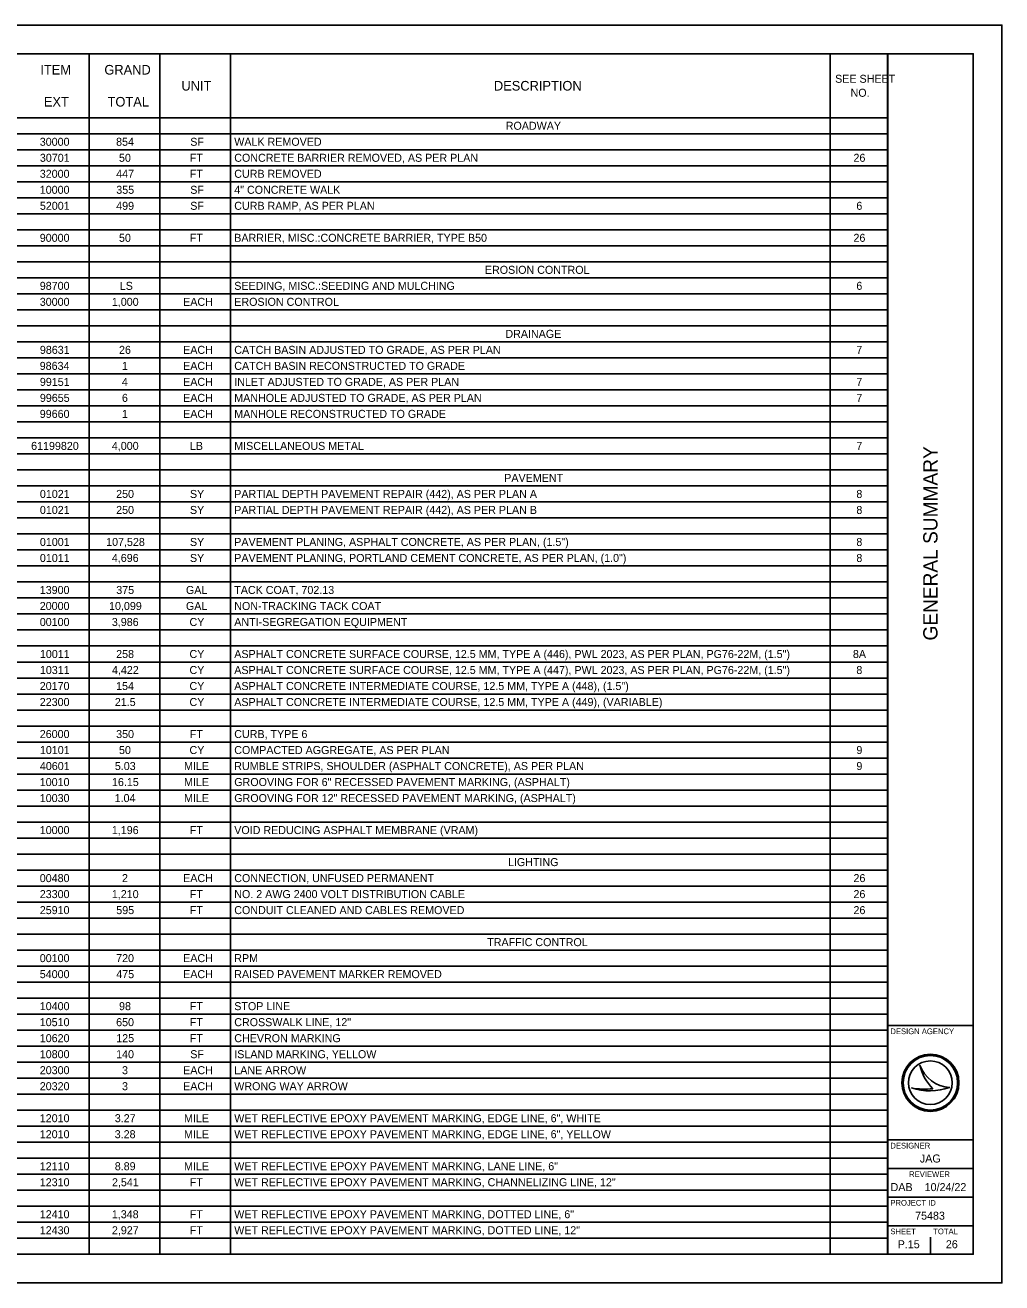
# Model space of a CAD drawing. Extents: x -32.9 to 34, y 0 to 22.
# Drawn here: x 16.92 to 34, y 0 to 22 of the extents above; entities that cross this region are included whole.
import ezdxf

# ---------------------------------------------------------------- set-up
doc = ezdxf.new("R2010")
doc.units = 0
for name, color, linetype in [('SH_Border', 7, 'Continuous'), ('SH_Cut_Line', 7, 'Continuous'), ('SH_Data', 7, 'Continuous'), ('SH_Text', 7, 'Continuous')]:
    doc.layers.add(name, color=color, linetype=linetype)

msp = doc.modelspace()

# ---------------------------------------------------------------- linework, layer by layer
at = {"layer": 'SH_Border'}
for p, q in [((32, 0.5), (32, 21.5)), ((32, 4.5), (33.5, 4.5)), ((32, 2.5), (33.5, 2.5)), ((32, 2), (33.5, 2)), ((32, 1.5), (33.5, 1.5)), ((32, 1), (33.5, 1))]:
    msp.add_line(p, q, dxfattribs=at)
msp.add_lwpolyline([(1.5, 21.5), (33.5, 21.5), (33.5, 0.5), (1.5, 0.5)], close=True, dxfattribs=at)
at = {"layer": 'SH_Cut_Line'}
msp.add_lwpolyline([(0, 0), (34, 0), (34, 22), (0, 22)], close=True, dxfattribs=at)
at = {"layer": 'SH_Data'}
for p, q in [((32.567, 3.81), (32.567, 3.81)), ((32.417, 3.41), (32.417, 3.41)), ((32.75, 3.5), (32.75, 3.5)), ((33.087, 3.419), (33.087, 3.419)), ((32.375, 0.675), (32.375, 0.675)), ((32.75, 0.5), (32.75, 0.8))]:
    msp.add_line(p, q, dxfattribs=at)
for radius in [0.5, 0.477, 0.477, 0.382]:
    msp.add_circle((32.75, 3.5), radius, dxfattribs=at)
for centre, radius, start, end in [((33.116, 3.998), 0.58, 198.9257, 198.9319), ((33.347, 3.97), 0.796, 191.6379, 191.6421), ((33.116, 3.998), 0.58, 198.9319, 267.1657), ((33.347, 3.97), 0.796, 191.6421, 226.0947), ((32.739, 4.37), 1.013, 251.4576, 290.0832), ((32.648, 4.654), 1.266, 259.4964, 259.4995), ((32.739, 4.37), 1.013, 251.4527, 251.4576), ((32.648, 4.654), 1.266, 259.4995, 276.6672)]:
    msp.add_arc(centre, radius, start, end, dxfattribs=at)
at = {"layer": 'SH_Text'}
for p, q in [((1.5, 21.5), (32.004, 21.5)), ((18.036, 21.5), (18.036, 0.5)), ((19.272, 21.5), (19.272, 0.5)), ((20.507, 21.5), (20.507, 0.5)), ((30.999, 21.5), (30.999, 0.5)), ((32.004, 21.5), (32.004, 0.5)), ((1.5, 20.38), (32.004, 20.38)), ((1.5, 20.1), (32.004, 20.1)), ((1.5, 19.82), (32.004, 19.82)), ((1.5, 19.54), (32.004, 19.54)), ((1.5, 19.26), (32.004, 19.26)), ((1.5, 18.98), (32.004, 18.98)), ((1.5, 18.7), (32.004, 18.7)), ((1.5, 18.42), (32.004, 18.42)), ((1.5, 18.14), (32.004, 18.14)), ((1.5, 17.86), (32.004, 17.86)), ((1.5, 17.58), (32.004, 17.58)), ((1.5, 17.3), (32.004, 17.3)), ((1.5, 17.02), (32.004, 17.02)), ((1.5, 16.74), (32.004, 16.74)), ((1.5, 16.46), (32.004, 16.46)), ((1.5, 16.18), (32.004, 16.18)), ((1.5, 15.9), (32.004, 15.9)), ((1.5, 15.62), (32.004, 15.62)), ((1.5, 15.34), (32.004, 15.34)), ((1.5, 15.06), (32.004, 15.06)), ((1.5, 14.78), (32.004, 14.78)), ((1.5, 14.5), (32.004, 14.5)), ((1.5, 14.22), (32.004, 14.22)), ((1.5, 13.94), (32.004, 13.94)), ((1.5, 13.66), (32.004, 13.66)), ((1.5, 13.38), (32.004, 13.38)), ((1.5, 13.1), (32.004, 13.1)), ((1.5, 12.82), (32.004, 12.82)), ((1.5, 12.54), (32.004, 12.54)), ((1.5, 12.26), (32.004, 12.26)), ((1.5, 11.98), (32.004, 11.98)), ((1.5, 11.7), (32.004, 11.7)), ((1.5, 11.42), (32.004, 11.42)), ((1.5, 11.14), (32.004, 11.14)), ((1.5, 10.86), (32.004, 10.86)), ((1.5, 10.58), (32.004, 10.58)), ((1.5, 10.3), (32.004, 10.3)), ((1.5, 10.02), (32.004, 10.02)), ((1.5, 9.74), (32.004, 9.74)), ((1.5, 9.46), (32.004, 9.46)), ((1.5, 9.18), (32.004, 9.18)), ((1.5, 8.9), (32.004, 8.9)), ((1.5, 8.62), (32.004, 8.62)), ((1.5, 8.34), (32.004, 8.34)), ((1.5, 8.06), (32.004, 8.06)), ((1.5, 7.78), (32.004, 7.78)), ((1.5, 7.5), (32.004, 7.5)), ((1.5, 7.22), (32.004, 7.22)), ((1.5, 6.94), (32.004, 6.94)), ((1.5, 6.66), (32.004, 6.66)), ((1.5, 6.38), (32.004, 6.38)), ((1.5, 6.1), (32.004, 6.1)), ((1.5, 5.82), (32.004, 5.82)), ((1.5, 5.54), (32.004, 5.54)), ((1.5, 5.26), (32.004, 5.26)), ((1.5, 4.98), (32.004, 4.98)), ((1.5, 4.7), (32.004, 4.7)), ((1.5, 4.42), (32.004, 4.42)), ((1.5, 4.14), (32.004, 4.14)), ((1.5, 3.86), (32.004, 3.86)), ((1.5, 3.58), (32.004, 3.58)), ((1.5, 3.3), (32.004, 3.3)), ((1.5, 3.02), (32.004, 3.02)), ((1.5, 2.74), (32.004, 2.74)), ((1.5, 2.46), (32.004, 2.46)), ((1.5, 2.18), (32.004, 2.18)), ((1.5, 1.9), (32.004, 1.9)), ((1.5, 1.62), (32.004, 1.62)), ((1.5, 1.34), (32.004, 1.34)), ((1.5, 1.06), (32.004, 1.06)), ((1.5, 0.78), (32.004, 0.78)), ((1.5, 0.5), (32.004, 0.5))]:
    msp.add_line(p, q, dxfattribs=at)

# ---------------------------------------------------------------- texts
at = {"layer": 'SH_Data'}
msp.add_text('GENERAL SUMMARY', height=0.25, rotation=90, dxfattribs=at).set_placement((32.875, 11.235))
for s, height, p in [('DESIGN AGENCY', 0.1, (32.05, 4.35)), ('DESIGNER', 0.1, (32.05, 2.35)), ('JAG', 0.14, (32.566, 2.105)), ('REVIEWER', 0.1, (32.378, 1.85)), ('DAB', 0.14, (32.054, 1.605)), ('10/24/22', 0.14, (32.65, 1.605)), ('PROJECT ID', 0.1, (32.05, 1.35)), ('75483', 0.14, (32.483, 1.105)), ('SHEET', 0.1, (32.05, 0.85)), ('TOTAL', 0.1, (32.8, 0.85)), ('P.15', 0.14, (32.178, 0.605)), ('26', 0.14, (33.021, 0.605))]:
    msp.add_text(s, height=height, dxfattribs=at).set_placement(p)
at = {"layer": 'SH_Text'}
for s, height, p in [('ITEM', 0.168, (17.181, 21.136)), ('GRAND', 0.168, (18.301, 21.136)), ('SEE SHEET ', 0.14, (31.084, 20.992)), ('UNIT', 0.168, (19.649, 20.856)), ('DESCRIPTION', 0.168, (25.115, 20.856)), ('EXT', 0.168, (17.242, 20.576)), ('TOTAL', 0.168, (18.357, 20.576)), ('NO.', 0.14, (31.354, 20.747)), ('ROADWAY', 0.14, (25.322, 20.17)), ('30000', 0.14, (17.171, 19.89)), ('854', 0.14, (18.506, 19.89)), ('SF', 0.14, (19.803, 19.89)), ('WALK REMOVED', 0.14, (20.573, 19.89)), ('30701', 0.14, (17.173, 19.61)), ('50', 0.14, (18.557, 19.61)), ('FT', 0.14, (19.796, 19.61)), ('CONCRETE BARRIER REMOVED, AS PER PLAN', 0.14, (20.573, 19.61)), ('26', 0.14, (31.405, 19.61)), ('32000', 0.14, (17.171, 19.33)), ('447', 0.14, (18.508, 19.33)), ('FT', 0.14, (19.796, 19.33)), ('CURB REMOVED', 0.14, (20.573, 19.33)), ('10000', 0.14, (17.171, 19.05)), ('355', 0.14, (18.509, 19.05)), ('SF', 0.14, (19.803, 19.05)), ('4" CONCRETE WALK', 0.14, (20.573, 19.05)), ('52001', 0.14, (17.173, 18.77)), ('499', 0.14, (18.508, 18.77)), ('SF', 0.14, (19.803, 18.77)), ('CURB RAMP, AS PER PLAN', 0.14, (20.573, 18.77)), ('6', 0.14, (31.455, 18.77)), ('90000', 0.14, (17.171, 18.21)), ('50', 0.14, (18.557, 18.21)), ('FT', 0.14, (19.796, 18.21)), ('BARRIER, MISC.:CONCRETE BARRIER, TYPE B50', 0.14, (20.573, 18.21)), ('26', 0.14, (31.405, 18.21)), ('EROSION CONTROL', 0.14, (24.957, 17.65)), ('98700', 0.14, (17.171, 17.37)), ('LS', 0.14, (18.57, 17.37)), ('SEEDING, MISC.:SEEDING AND MULCHING', 0.14, (20.573, 17.37)), ('6', 0.14, (31.455, 17.37)), ('30000', 0.14, (17.171, 17.09)), ('1,000', 0.14, (18.432, 17.09)), ('EACH', 0.14, (19.679, 17.09)), ('EROSION CONTROL', 0.14, (20.573, 17.09)), ('DRAINAGE', 0.14, (25.316, 16.53)), ('98631', 0.14, (17.173, 16.25)), ('26', 0.14, (18.557, 16.25)), ('EACH', 0.14, (19.679, 16.25)), ('CATCH BASIN ADJUSTED TO GRADE, AS PER PLAN', 0.14, (20.573, 16.25)), ('7', 0.14, (31.455, 16.25)), ('98634', 0.14, (17.17, 15.97)), ('1', 0.14, (18.609, 15.97)), ('EACH', 0.14, (19.679, 15.97)), ('CATCH BASIN RECONSTRUCTED TO GRADE', 0.14, (20.573, 15.97)), ('99151', 0.14, (17.173, 15.69)), ('4', 0.14, (18.607, 15.69)), ('EACH', 0.14, (19.679, 15.69)), ('INLET ADJUSTED TO GRADE, AS PER PLAN', 0.14, (20.573, 15.69)), ('7', 0.14, (31.455, 15.69)), ('99655', 0.14, (17.173, 15.41)), ('6', 0.14, (18.608, 15.41)), ('EACH', 0.14, (19.679, 15.41)), ('MANHOLE ADJUSTED TO GRADE, AS PER PLAN', 0.14, (20.573, 15.41)), ('7', 0.14, (31.455, 15.41)), ('99660', 0.14, (17.171, 15.13)), ('1', 0.14, (18.609, 15.13)), ('EACH', 0.14, (19.679, 15.13)), ('MANHOLE RECONSTRUCTED TO GRADE', 0.14, (20.573, 15.13)), ('61199820', 0.14, (17.02, 14.57)), ('4,000', 0.14, (18.432, 14.57)), ('LB', 0.14, (19.798, 14.57)), ('MISCELLANEOUS METAL', 0.14, (20.573, 14.57)), ('7', 0.14, (31.455, 14.57)), ('PAVEMENT', 0.14, (25.296, 14.01)), ('01021', 0.14, (17.173, 13.73)), ('250', 0.14, (18.507, 13.73)), ('SY', 0.14, (19.798, 13.73)), ('PARTIAL DEPTH PAVEMENT REPAIR (442), AS PER PLAN A', 0.14, (20.573, 13.73)), ('8', 0.14, (31.455, 13.73)), ('01021', 0.14, (17.173, 13.45)), ('250', 0.14, (18.507, 13.45)), ('SY', 0.14, (19.798, 13.45)), ('PARTIAL DEPTH PAVEMENT REPAIR (442), AS PER PLAN B', 0.14, (20.573, 13.45)), ('8', 0.14, (31.455, 13.45)), ('01001', 0.14, (17.173, 12.89)), ('107,528', 0.14, (18.332, 12.89)), ('SY', 0.14, (19.798, 12.89)), ('PAVEMENT PLANING, ASPHALT CONCRETE, AS PER PLAN, (1.5")', 0.14, (20.573, 12.89)), ('8', 0.14, (31.455, 12.89)), ('01011', 0.14, (17.173, 12.61)), ('4,696', 0.14, (18.432, 12.61)), ('SY', 0.14, (19.798, 12.61)), ('PAVEMENT PLANING, PORTLAND CEMENT CONCRETE, AS PER PLAN, (1.0")', 0.14, (20.573, 12.61)), ('8', 0.14, (31.455, 12.61)), ('13900', 0.14, (17.171, 12.05)), ('375', 0.14, (18.509, 12.05)), ('GAL', 0.14, (19.728, 12.05)), ('TACK COAT, 702.13', 0.14, (20.573, 12.05)), ('20000', 0.14, (17.171, 11.77)), ('10,099', 0.14, (18.383, 11.77)), ('GAL', 0.14, (19.728, 11.77)), ('NON-TRACKING TACK COAT', 0.14, (20.573, 11.77)), ('00100', 0.14, (17.171, 11.49)), ('3,986', 0.14, (18.432, 11.49)), ('CY', 0.14, (19.79, 11.49)), ('ANTI-SEGREGATION EQUIPMENT', 0.14, (20.573, 11.49)), ('10011', 0.14, (17.173, 10.93)), ('258', 0.14, (18.507, 10.93)), ('CY', 0.14, (19.79, 10.93)), ('ASPHALT CONCRETE SURFACE COURSE, 12.5 MM, TYPE A (446), PWL 2023, AS PER PLAN, PG76-22M, (1.5")', 0.14, (20.573, 10.93)), ('8A', 0.14, (31.395, 10.93)), ('10311', 0.14, (17.173, 10.65)), ('4,422', 0.14, (18.434, 10.65)), ('CY', 0.14, (19.79, 10.65)), ('ASPHALT CONCRETE SURFACE COURSE, 12.5 MM, TYPE A (447), PWL 2023, AS PER PLAN, PG76-22M, (1.5")', 0.14, (20.573, 10.65)), ('8', 0.14, (31.455, 10.65)), ('20170', 0.14, (17.171, 10.37)), ('154', 0.14, (18.506, 10.37)), ('CY', 0.14, (19.79, 10.37)), ('ASPHALT CONCRETE INTERMEDIATE COURSE, 12.5 MM, TYPE A (448), (1.5")', 0.14, (20.573, 10.37)), ('22300', 0.14, (17.171, 10.09)), ('21.5', 0.14, (18.484, 10.09)), ('CY', 0.14, (19.79, 10.09)), ('ASPHALT CONCRETE INTERMEDIATE COURSE, 12.5 MM, TYPE A (449), (VARIABLE)', 0.14, (20.573, 10.09)), ('26000', 0.14, (17.171, 9.53)), ('350', 0.14, (18.507, 9.53)), ('FT', 0.14, (19.796, 9.53)), ('CURB, TYPE 6', 0.14, (20.573, 9.53)), ('10101', 0.14, (17.173, 9.25)), ('50', 0.14, (18.557, 9.25)), ('CY', 0.14, (19.79, 9.25)), ('COMPACTED AGGREGATE, AS PER PLAN', 0.14, (20.573, 9.25)), ('9', 0.14, (31.456, 9.25)), ('40601', 0.14, (17.173, 8.97)), ('5.03', 0.14, (18.484, 8.97)), ('MILE', 0.14, (19.695, 8.97)), ('RUMBLE STRIPS, SHOULDER (ASPHALT CONCRETE), AS PER PLAN', 0.14, (20.573, 8.97)), ('9', 0.14, (31.456, 8.97)), ('10010', 0.14, (17.171, 8.69)), ('16.15', 0.14, (18.434, 8.69)), ('MILE', 0.14, (19.695, 8.69)), ('GROOVING FOR 6" RECESSED PAVEMENT MARKING, (ASPHALT)', 0.14, (20.573, 8.69)), ('10030', 0.14, (17.171, 8.41)), ('1.04', 0.14, (18.481, 8.41)), ('MILE', 0.14, (19.695, 8.41)), ('GROOVING FOR 12" RECESSED PAVEMENT MARKING, (ASPHALT)', 0.14, (20.573, 8.41)), ('10000', 0.14, (17.171, 7.85)), ('1,196', 0.14, (18.432, 7.85)), ('FT', 0.14, (19.796, 7.85)), ('VOID REDUCING ASPHALT MEMBRANE (VRAM)', 0.14, (20.573, 7.85)), ('LIGHTING', 0.14, (25.361, 7.29)), ('00480', 0.14, (17.171, 7.01)), ('2', 0.14, (18.609, 7.01)), ('EACH', 0.14, (19.679, 7.01)), ('CONNECTION, UNFUSED PERMANENT', 0.14, (20.573, 7.01)), ('26', 0.14, (31.405, 7.01)), ('23300', 0.14, (17.171, 6.73)), ('1,210', 0.14, (18.432, 6.73)), ('FT', 0.14, (19.796, 6.73)), ('NO. 2 AWG 2400 VOLT DISTRIBUTION CABLE', 0.14, (20.573, 6.73)), ('26', 0.14, (31.405, 6.73)), ('25910', 0.14, (17.171, 6.45)), ('595', 0.14, (18.509, 6.45)), ('FT', 0.14, (19.796, 6.45)), ('CONDUIT CLEANED AND CABLES REMOVED', 0.14, (20.573, 6.45)), ('26', 0.14, (31.405, 6.45)), ('TRAFFIC CONTROL', 0.14, (24.998, 5.89)), ('00100', 0.14, (17.171, 5.61)), ('720', 0.14, (18.507, 5.61)), ('EACH', 0.14, (19.679, 5.61)), ('RPM', 0.14, (20.573, 5.61)), ('54000', 0.14, (17.171, 5.33)), ('475', 0.14, (18.509, 5.33)), ('EACH', 0.14, (19.679, 5.33)), ('RAISED PAVEMENT MARKER REMOVED', 0.14, (20.573, 5.33)), ('10400', 0.14, (17.171, 4.77)), ('98', 0.14, (18.558, 4.77)), ('FT', 0.14, (19.796, 4.77)), ('STOP LINE', 0.14, (20.573, 4.77)), ('10510', 0.14, (17.171, 4.49)), ('650', 0.14, (18.507, 4.49)), ('FT', 0.14, (19.796, 4.49)), ('CROSSWALK LINE, 12"', 0.14, (20.573, 4.49)), ('10620', 0.14, (17.171, 4.21)), ('125', 0.14, (18.509, 4.21)), ('FT', 0.14, (19.796, 4.21)), ('CHEVRON MARKING', 0.14, (20.573, 4.21)), ('10800', 0.14, (17.171, 3.93)), ('140', 0.14, (18.507, 3.93)), ('SF', 0.14, (19.803, 3.93)), ('ISLAND MARKING, YELLOW', 0.14, (20.573, 3.93)), ('20300', 0.14, (17.171, 3.65)), ('3', 0.14, (18.61, 3.65)), ('EACH', 0.14, (19.679, 3.65)), ('LANE ARROW', 0.14, (20.573, 3.65)), ('20320', 0.14, (17.171, 3.37)), ('3', 0.14, (18.61, 3.37)), ('EACH', 0.14, (19.679, 3.37)), ('WRONG WAY ARROW', 0.14, (20.573, 3.37)), ('12010', 0.14, (17.171, 2.81)), ('3.27', 0.14, (18.483, 2.81)), ('MILE', 0.14, (19.695, 2.81)), ('WET REFLECTIVE EPOXY PAVEMENT MARKING, EDGE LINE, 6", WHITE', 0.14, (20.573, 2.81)), ('12010', 0.14, (17.171, 2.53)), ('3.28', 0.14, (18.482, 2.53)), ('MILE', 0.14, (19.695, 2.53)), ('WET REFLECTIVE EPOXY PAVEMENT MARKING, EDGE LINE, 6", YELLOW', 0.14, (20.573, 2.53)), ('12110', 0.14, (17.171, 1.97)), ('8.89', 0.14, (18.483, 1.97)), ('MILE', 0.14, (19.695, 1.97)), ('WET REFLECTIVE EPOXY PAVEMENT MARKING, LANE LINE, 6"', 0.14, (20.573, 1.97)), ('12310', 0.14, (17.171, 1.69)), ('2,541', 0.14, (18.434, 1.69)), ('FT', 0.14, (19.796, 1.69)), ('WET REFLECTIVE EPOXY PAVEMENT MARKING, CHANNELIZING LINE, 12"', 0.14, (20.573, 1.69)), ('12410', 0.14, (17.171, 1.13)), ('1,348', 0.14, (18.432, 1.13)), ('FT', 0.14, (19.796, 1.13)), ('WET REFLECTIVE EPOXY PAVEMENT MARKING, DOTTED LINE, 6"', 0.14, (20.573, 1.13)), ('12430', 0.14, (17.171, 0.85)), ('2,927', 0.14, (18.433, 0.85)), ('FT', 0.14, (19.796, 0.85)), ('WET REFLECTIVE EPOXY PAVEMENT MARKING, DOTTED LINE, 12"', 0.14, (20.573, 0.85))]:
    msp.add_text(s, height=height, dxfattribs=at).set_placement(p)

doc.saveas('drawing.dxf')
